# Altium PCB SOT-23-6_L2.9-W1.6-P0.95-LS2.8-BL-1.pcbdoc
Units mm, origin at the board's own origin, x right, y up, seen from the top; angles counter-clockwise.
Board outline 15.71 x 16.75 mm, 2 copper layers (Top Layer, Bottom Layer), stack 0 mm thick; 1 components, 0 nets, 6 pads, 0 vias.
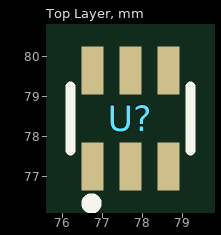
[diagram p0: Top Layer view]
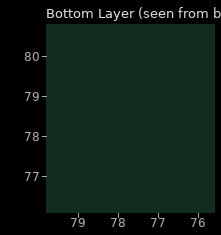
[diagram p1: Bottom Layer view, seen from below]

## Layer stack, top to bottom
Top Layer: signal copper (thickness not stored)
Bottom Layer: signal copper (thickness not stored)

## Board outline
85.56,69.85 69.85,69.85 69.85,86.602 85.56,86.602

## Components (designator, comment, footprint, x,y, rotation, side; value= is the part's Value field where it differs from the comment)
U? "" SOT-23-6_L2.9-W1.6-P0.95-LS2.8-BL-1 77.71,78.452 r0 top

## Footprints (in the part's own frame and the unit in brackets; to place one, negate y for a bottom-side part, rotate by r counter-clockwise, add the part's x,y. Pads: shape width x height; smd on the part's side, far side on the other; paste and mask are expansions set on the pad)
SOT-23-6_L2.9-W1.6-P0.95-LS2.8-BL-1 [mm]
  rect 0.55x1.2 smd: 1(-0.95,-1.2) 2(0,-1.2) 3(0.95,-1.2) 4(0.95,1.2) 5(0,1.2) 6(-0.95,1.2)
  silkscreen extent -1.5,-2.25 1.5,0.8

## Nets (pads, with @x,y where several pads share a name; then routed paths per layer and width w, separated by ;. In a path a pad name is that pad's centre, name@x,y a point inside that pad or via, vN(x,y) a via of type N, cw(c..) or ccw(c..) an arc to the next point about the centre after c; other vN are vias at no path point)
pads on no net: U?.1 U?.2 U?.3 U?.4 U?.5 U?.6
